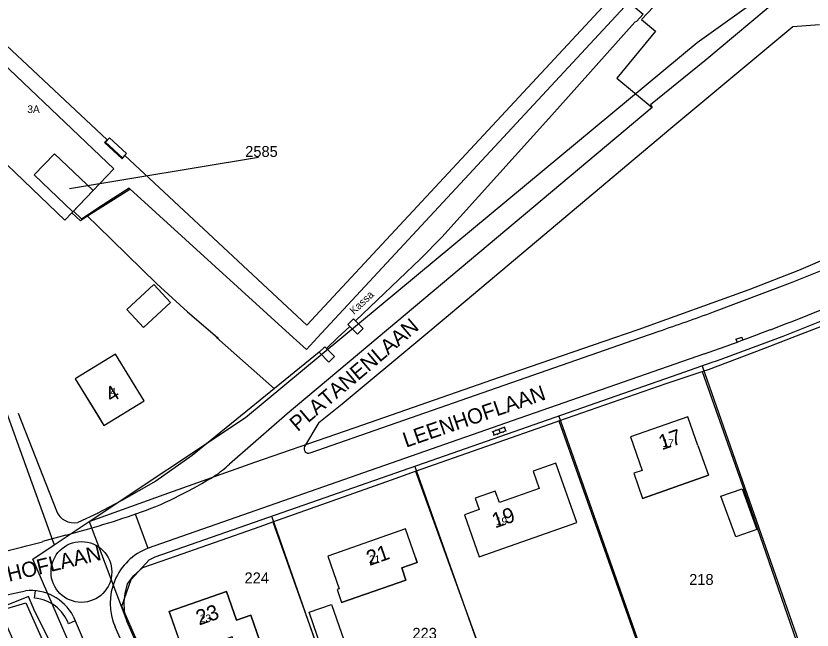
# Model space of a CAD drawing. Extents: x 148816 to 151297, y 399515 to 402500.
# Drawn here: x 149486.6 to 149617.6, y 400451.8 to 400552.9 of the extents above; entities that cross this region are included whole.
import ezdxf

# ---------------------------------------------------------------- set-up
doc = ezdxf.new("R2010")
doc.units = 0
for name, color, linetype in [('B01 Hoofdgebouw  [D] Norm', 7, 'Continuous'), ('B01 Hoofdgebouw  [T] Norm', 7, 'Continuous'), ('B01 hoofgebouw', 7, 'Continuous'), ('B02 Bijgebouw  [D] Norm', 7, 'Continuous'), ('G01 perceelsgrens', 7, 'Continuous'), ('G02 sectiegrens', 7, 'Continuous'), ('Q01 Spoorrail  [D] Norm', 7, 'Continuous'), ('S02 Open verharding  Norm', 7, 'Continuous'), ('S05 Water  Norm', 7, 'Continuous'), ('T04 Haag heg  [D] Gem', 7, 'Continuous'), ('T09 Insteek water  [T] Norm', 7, 'Continuous'), ('V00 Kant verharding algemeen  [T] Norm', 7, 'Continuous'), ('V00 Kant verharding algemeen secundair  [T] Gem', 7, 'Continuous'), ('Z01 perceelnummer', 7, 'Continuous'), ('Z02 huisnummer', 7, 'Continuous'), ('Z02 Huisnummer  [Tekst] Norm', 7, 'Continuous'), ('Z06 straatnaam', 7, 'Continuous'), ('Z19 Overige Tekst  [Tekst] Gem', 7, 'Continuous')]:
    doc.layers.add(name, color=color, linetype=linetype)

msp = doc.modelspace()

# ---------------------------------------------------------------- linework, layer by layer
at = {"layer": 'B01 Hoofdgebouw  [D] Norm'}
for points in [[(149507.58, 400501.65), (149512.04, 400505.78), (149509.3, 400508.74), (149504.84, 400504.61)], [(149602.55, 400473.88), (149606.09, 400475.08), (149608.46, 400468.4), (149605, 400467.2)]]:
    msp.add_lwpolyline(points, close=True, dxfattribs=at)
for points in [[(149598.8, 400482.25), (149600.54, 400477.32)], [(149589.68, 400473.48), (149600.54, 400477.32)], [(149552.33, 400463.77), (149552.62, 400462.98), (149550.07, 400462.08), (149550.71, 400460.08)]]:
    msp.add_lwpolyline(points, dxfattribs=at)
at = {"layer": 'B01 Hoofdgebouw  [T] Norm'}
for p, q in [((149502.97, 400497.28), (149500, 400495.47)), ((149507.68, 400489.6), (149502.97, 400497.28)), ((149500, 400495.47), (149496.33, 400493.22)), ((149496.33, 400493.22), (149500, 400487.26)), ((149501.06, 400485.54), (149507.68, 400489.6)), ((149500, 400487.26), (149501.06, 400485.54)), ((149597.14, 400486.97), (149587.69, 400483.65)), ((149598.8, 400482.25), (149597.14, 400486.97)), ((149587.69, 400483.65), (149589.63, 400478.14)), ((149589.63, 400478.14), (149588.22, 400477.65)), ((149588.22, 400477.65), (149589.68, 400473.48)), ((149550.67, 400468.49), (149537.91, 400464.01)), ((149552.33, 400463.77), (149550.67, 400468.49)), ((149537.91, 400464.01), (149539.79, 400458.65)), ((149550.71, 400460.08), (149540.16, 400456.38)), ((149539.79, 400458.65), (149539.41, 400458.52)), ((149539.41, 400458.52), (149540.16, 400456.38)), ((149521.22, 400458.18), (149511.79, 400454.88)), ((149522.87, 400453.47), (149521.22, 400458.18)), ((149511.79, 400454.88), (149514.24, 400447.93)), ((149525.23, 400454.3), (149522.87, 400453.47)), ((149528.22, 400445.75), (149525.23, 400454.3))]:
    msp.add_line(p, q, dxfattribs=at)
for points in [[(149494.66, 400519.34), (149476.95, 400536.22), (149479.18, 400538.62), (149472.78, 400544.7), (149478.55, 400550.7), (149502.67, 400527.75)], [(149541.18, 400502.15), (149542.13, 400503.09), (149543.71, 400501.47), (149542.76, 400500.54)], [(149536.46, 400497.57), (149537.4, 400498.48), (149538.98, 400496.86), (149538.04, 400495.95)], [(149560.37, 400470.82), (149562.82, 400463.88), (149578.84, 400469.53), (149575.39, 400479.32), (149571.67, 400478.01), (149572.67, 400475.16), (149566.12, 400472.85), (149565.45, 400474.73), (149562.15, 400473.57), (149562.82, 400471.68)]]:
    msp.add_lwpolyline(points, close=True, dxfattribs=at)
msp.add_lwpolyline([(149496.04, 400520.79), (149497.37, 400519.56), (149498.68, 400520.44), (149500, 400521.31), (149502.62, 400522.98), (149505.24, 400524.65), (149505.29, 400524.56), (149505.34, 400524.47), (149505.32, 400524.37), (149502.66, 400522.68), (149500, 400521), (149498.38, 400519.97), (149497.22, 400519.2), (149495.8, 400520.54)], dxfattribs=at)
at = {"layer": 'B01 hoofgebouw'}
for points in [[(149494.66, 400519.34), (149476.95, 400536.22), (149479.18, 400538.62), (149472.78, 400544.7), (149478.55, 400550.7), (149502.67, 400527.75), (149494.66, 400519.34)], [(149542.13, 400503.09), (149541.18, 400502.15), (149542.76, 400500.54), (149543.71, 400501.47), (149542.13, 400503.09)], [(149538.98, 400496.86), (149537.4, 400498.48), (149536.46, 400497.57), (149538.04, 400495.95), (149538.98, 400496.86)], [(149501.06, 400485.54), (149507.68, 400489.6), (149502.97, 400497.28), (149496.33, 400493.22), (149501.06, 400485.54)], [(149598.8, 400482.25), (149597.14, 400486.97), (149587.69, 400483.65), (149589.63, 400478.14), (149588.22, 400477.65), (149589.68, 400473.48)], [(149598.8, 400482.25), (149600.54, 400477.32), (149589.68, 400473.48)], [(149560.37, 400470.82), (149562.82, 400463.88), (149578.84, 400469.53), (149575.39, 400479.32), (149571.67, 400478.01), (149572.67, 400475.16), (149566.12, 400472.85), (149565.45, 400474.73), (149562.15, 400473.57), (149562.82, 400471.68), (149560.37, 400470.82)], [(149552.33, 400463.77), (149550.67, 400468.49), (149537.91, 400464.01), (149539.79, 400458.65), (149539.41, 400458.52), (149540.16, 400456.38)], [(149540.16, 400456.38), (149550.71, 400460.08), (149550.07, 400462.08), (149552.62, 400462.98), (149552.33, 400463.77)], [(149514.24, 400447.93), (149511.79, 400454.88), (149521.22, 400458.18), (149522.87, 400453.47), (149525.23, 400454.3), (149528.22, 400445.75), (149521.59, 400443.42), (149520.26, 400447.19), (149523.08, 400448.18), (149522.18, 400450.73), (149514.24, 400447.93)]]:
    msp.add_lwpolyline(points, dxfattribs=at)
at = {"layer": 'B02 Bijgebouw  [D] Norm'}
msp.add_lwpolyline([(149538.51, 400456.08), (149541.35, 400447.9), (149537.65, 400446.61), (149534.81, 400454.79)], close=True, dxfattribs=at)
at = {"layer": 'G01 perceelsgrens'}
for points in [[(149585.1, 400500), (149588.96, 400501.33), (149607.2, 400507.89), (149615.4, 400511.08), (149626.35, 400515.79), (149637.93, 400520.66), (149651.03, 400526.94), (149663.1, 400532.79), (149671.89, 400537.01), (149681.95, 400542.2), (149690.83, 400547.07), (149700.46, 400552.39), (149707.9, 400557.19), (149723.69, 400567.14), (149737.44, 400576.57), (149750.21, 400585.62), (149757.63, 400591.32), (149761.44, 400594.33), (149777.44, 400607.06), (149785.34, 400613.6), (149796.42, 400622.86), (149800.98, 400627.09)], [(149499.28, 400524.2), (149495.97, 400520.72), (149489.6, 400526.79), (149492.91, 400530.26), (149499.28, 400524.2)], [(149614.27, 400500), (149619.31, 400501.94), (149627.51, 400505.33)], [(149557.27, 400316.7), (149544.05, 400339.04), (149535.31, 400354.65), (149530.26, 400364.77), (149518.78, 400390.82), (149509.9, 400411.81), (149499.23, 400436.04), (149489.7, 400454.93), (149488.63, 400457.35), (149484.98, 400455.88), (149481.33, 400464.99), (149484.65, 400466.32), (149483.01, 400470.01), (149474.3, 400500)], [(149480.52, 400500), (149492.87, 400465.86)], [(149498.63, 400469.7), (149510.98, 400474.18), (149525.87, 400479.51), (149543.65, 400485.61), (149566.16, 400493.49), (149585.1, 400500)], [(149599.49, 400494.4), (149600.54, 400494.75), (149609.64, 400498.21), (149614.27, 400500)], [(149575.93, 400486.31), (149593.57, 400492.44), (149599.49, 400494.4)], [(149599.49, 400494.4), (149606.48, 400474.56), (149617.48, 400442.84)], [(149552.34, 400478), (149575.47, 400486.15), (149575.93, 400486.31)], [(149575.93, 400486.31), (149586.26, 400456.98), (149596.62, 400427.62)], [(149528.86, 400469.64), (149548.36, 400476.59), (149552.34, 400478)], [(149552.34, 400478), (149565.98, 400440.23)], [(149498.63, 400469.7), (149504.85, 400453.29)], [(149504.85, 400453.29), (149504.45, 400454.98), (149504.39, 400456.47), (149504.55, 400457.84), (149504.95, 400459.45), (149505.92, 400460.75), (149507.48, 400462.13), (149511.73, 400463.61), (149526.77, 400468.89), (149528.86, 400469.64)], [(149528.86, 400469.64), (149537.53, 400445.29)], [(149513.06, 400434.7), (149504.85, 400453.29)]]:
    msp.add_lwpolyline(points, dxfattribs=at)
at = {"layer": 'G02 sectiegrens'}
for points in [[(149540.2, 400500), (149564.79, 400520.43), (149598.68, 400548.56), (149619.97, 400563.9), (149644.11, 400584.23), (149688.7, 400621.22), (149778.93, 400661.52)], [(149498.63, 400469.7), (149524.37, 400486.85), (149540.2, 400500)], [(149492.87, 400465.86), (149497.84, 400469.17), (149498.63, 400469.7)], [(149529.76, 400370.07), (149489.38, 400463.53), (149492.87, 400465.86)]]:
    msp.add_lwpolyline(points, dxfattribs=at)
at = {"layer": 'Q01 Spoorrail  [D] Norm'}
for centre, radius, start, end in [((150635.92, 400924.19), 1248.76, 202.08931, 203.99655), ((150415.35, 400828.93), 1013.77, 201.72769, 205.4551), ((150415.35, 400828.93), 1012.27, 201.72769, 205.27615), ((150635.92, 400924.19), 1250.26, 202.08931, 203.99655)]:
    msp.add_arc(centre, radius, start, end, dxfattribs=at)
at = {"layer": 'S02 Open verharding  Norm'}
for p, q in [((149564.94, 400484.48), (149567.1, 400485.28)), ((149565.29, 400483.97), (149565.08, 400484.53)), ((149565.15, 400483.92), (149567.31, 400484.72)), ((149565.5, 400484.85), (149565.55, 400484.71)), ((149566.02, 400484.88), (149566.23, 400484.32)), ((149566.44, 400485.19), (149566.49, 400485.05)), ((149566.7, 400484.49), (149566.75, 400484.35)), ((149567.17, 400484.66), (149566.96, 400485.23)), ((149565.76, 400484.14), (149565.81, 400484))]:
    msp.add_line(p, q, dxfattribs=at)
at = {"layer": 'S05 Water  Norm'}
for p, q in [((149605.05, 400499.71), (149605.83, 400500)), ((149605.05, 400499.71), (149605.23, 400499.24)), ((149605.83, 400500), (149605.99, 400500.06)), ((149605.99, 400500.06), (149606.01, 400500)), ((149606.01, 400500), (149606.16, 400499.59))]:
    msp.add_line(p, q, dxfattribs=at)
at = {"layer": 'T04 Haag heg  [D] Gem'}
for p, q in [((149539.54, 400500), (149541.53, 400501.79)), ((149519.58, 400500), (149529.12, 400491.55)), ((149599.51, 400495.35), (149617.57, 400443.57)), ((149575.93, 400487.07), (149596.61, 400428.27)), ((149552.24, 400478.75), (149565.67, 400440.85)), ((149528.69, 400470.47), (149537.29, 400445.84))]:
    msp.add_line(p, q, dxfattribs=at)
for points in [[(149536.21, 400500), (149587.44, 400555.21), (149589.78, 400553.24), (149588.67, 400552.01), (149588.41, 400551.91), (149574.73, 400536.63), (149556.68, 400516.55), (149553.16, 400512.93), (149542.48, 400502.73)], [(149505.34, 400524.47), (149532.19, 400500)], [(149500, 400518.37), (149498.36, 400519.96)], [(149500, 400518.37), (149509.7, 400508.9), (149510.36, 400508.29), (149514.84, 400504.21), (149519.77, 400500)], [(149519.77, 400500), (149519.91, 400499.88)], [(149532.19, 400500), (149534.37, 400498.01), (149536.21, 400500)], [(149539.54, 400500), (149537.68, 400498.19)], [(149536.46, 400497.57), (149515.58, 400480.58), (149509.6, 400476.34), (149504.03, 400473.18), (149499.93, 400471.06)], [(149486.94, 400487.54), (149493.25, 400471.46)], [(149500.14, 400471.11), (149496.76, 400469.53)]]:
    msp.add_lwpolyline(points, dxfattribs=at)
msp.add_lwpolyline([(149504.1, 400529.59), (149501.32, 400532.18), (149501.99, 400532.89), (149504.77, 400530.3)], close=True, dxfattribs=at)
msp.add_arc((149496.21, 400472.69), 3.21, 202.5894, 279.8104, dxfattribs=at)
at = {"layer": 'T09 Insteek water  [T] Norm'}
msp.add_lwpolyline([(149483.96, 400455.08), (149488.22, 400456.33), (149509.12, 400409.42), (149518.5, 400389.73), (149527, 400373.04), (149523.19, 400370.83), (149514.55, 400387.79), (149505.13, 400407.58), (149496.19, 400427.49)], close=True, dxfattribs=at)
at = {"layer": 'V00 Kant verharding algemeen  [T] Norm'}
for p, q in [((149614.53, 400557.8), (149599.95, 400545.55)), ((149614.42, 400551.21), (149618.77, 400551.52)), ((149594.35, 400534.44), (149614.42, 400551.21)), ((149599.95, 400545.55), (149591.01, 400538.32)), ((149591.01, 400538.32), (149591.28, 400537.89)), ((149591.28, 400537.89), (149546.17, 400500)), ((149557.02, 400503.06), (149594.35, 400534.44)), ((149553.35, 400500), (149557.02, 400503.06)), ((149546.17, 400500), (149531.21, 400487.43)), ((149540.24, 400489.07), (149553.35, 400500)), ((149536.43, 400486), (149540.24, 400489.07)), ((149479.58, 400456.43), (149488.15, 400458.3)), ((149533.88, 400387.78), (149504, 400455.8))]:
    msp.add_line(p, q, dxfattribs=at)
for points in [[(149534.45, 400502.05), (149585.36, 400556.83), (149502.54, 400634.12), (149451.56, 400579.29), (149480.3, 400552.55)], [(149593.41, 400556.55), (149589.48, 400552.34), (149591.8, 400550.43), (149585.43, 400542.72), (149591.28, 400537.89)], [(149479.84, 400552.07), (149482.8, 400549.23), (149483.24, 400549.74), (149501.62, 400532.57), (149501.15, 400532.12), (149504.05, 400529.44), (149504.48, 400529.95), (149534.45, 400502.05)], [(149614.03, 400509), (149622.8, 400512.49)], [(149601.35, 400504.23), (149614.03, 400509)], [(149612.81, 400500.23), (149621.31, 400503.61)], [(149589.37, 400500), (149592.39, 400501.05)], [(149535.01, 400481.03), (149589.37, 400500)], [(149599.87, 400497.3), (149568.21, 400486.27), (149508.32, 400465.32)], [(149595.52, 400493.97), (149600.39, 400495.66)], [(149504, 400455.8), (149505.53, 400460.18), (149508.5, 400463.4), (149509.52, 400463.9), (149558.38, 400480.99), (149595.52, 400493.97)], [(149531.21, 400487.43), (149521.71, 400479.18)], [(149536.43, 400486), (149534.08, 400482.04)], [(149494.82, 400467.46), (149490.95, 400466.4)], [(149489.67, 400457.09), (149489.79, 400458.31)], [(149496.34, 400453.34), (149495.26, 400452.85)], [(149496.01, 400454.14), (149500.31, 400444.02), (149526.61, 400384.35)], [(149531.91, 400386.53), (149502.89, 400452.39)]]:
    msp.add_lwpolyline(points, dxfattribs=at)
for centre, radius, start, end in [((149427.39, 400984.12), 516.46, 290.7918, 292.092), ((149460.56, 400887.65), 408.46, 288.8291, 290.1632), ((149422.11, 400997.3), 530.65, 290.422, 290.8194), ((149323.89, 401266.33), 818.77, 290.61787, 290.66293), ((149422.11, 400997.3), 530.65, 289.5711, 290.422), ((149323.89, 401266.33), 818.77, 289.73676, 290.61787), ((149534.72, 400481.69), 0.724, 151.349, 293.5023), ((149511.94, 400488.97), 13.83, 302.2011, 314.9377), ((149483.87, 400533.6), 66.56, 296.3961, 302.1743), ((149488.59, 400522.58), 54.59, 290.004, 297.1053), ((149451.73, 400629.95), 168.1, 284.8504, 289.2884), ((149444.88, 400632.14), 172.03, 280.7527, 285.5311), ((149511.75, 400456.27), 9.66, 110.7606, 203.634), ((149489.04, 400450.48), 7.87, 27.7036, 96.4737), ((149489.16, 400450.62), 6.49, 20.0574, 85.461)]:
    msp.add_arc(centre, radius, start, end, dxfattribs=at)
at = {"layer": 'V00 Kant verharding algemeen secundair  [T] Gem'}
msp.add_lwpolyline([(149508.32, 400465.3), (149506.25, 400470.9)], dxfattribs=at)
msp.add_circle((149497.36, 400461.41), 5, dxfattribs=at)
at = {"layer": 'Z01 perceelnummer'}
msp.add_lwpolyline([(149526.48, 400529.63), (149495.39, 400524.48)], dxfattribs=at)

# ---------------------------------------------------------------- texts
for s, p in [('2585', (149524.31, 400529.73)), ('224', (149524.2, 400459.53)), ('218', (149597.35, 400459.27)), ('223', (149551.82, 400450.41))]:
    msp.add_text(s, height=1.8, dxfattribs=at).set_placement(p)
at = {"layer": 'Z02 huisnummer'}
for s, rotation, p in [('4', 31.5137, (149502.27, 400489.22)), ('17', 19.3225, (149592.84, 400481.43)), ('19', 19.3955, (149565.42, 400468.57)), ('21', 19.3225, (149544.76, 400462.39)), ('23', 19.2684, (149516.72, 400452.58))]:
    msp.add_text(s, height=2.5, rotation=rotation, dxfattribs=at).set_placement(p)
at = {"layer": 'Z02 Huisnummer  [Tekst] Norm'}
for s, p in [('3A', (149488.46, 400536.96)), ('4', (149502.14, 400490.48)), ('17', (149592.95, 400482)), ('19', (149565.54, 400469.14)), ('21', (149544.66, 400462.88)), ('23', (149516.83, 400453.15))]:
    msp.add_text(s, height=1.25, dxfattribs=at).set_placement(p)
at = {"layer": 'Z06 straatnaam'}
for s, rotation, p in [('PLATANENLAAN', 40.2532, (149532.94, 400484.42)), ('LEENHOFLAAN', 19.0331, (149550.76, 400481.86)), ('LEENHOFLAAN', 13.3553, (149476.94, 400457.77))]:
    msp.add_text(s, height=2.5, rotation=rotation, dxfattribs=at).set_placement(p)
at = {"layer": 'Z19 Overige Tekst  [Tekst] Gem'}
msp.add_text('Kassa', height=1.25, rotation=43.4788, dxfattribs=at).set_placement((149542.21, 400503.72))

doc.saveas('drawing.dxf')
